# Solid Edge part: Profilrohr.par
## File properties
Username: bmolnar
Dokumentum tartalom típus: 0
Author: bmolnar
Last saved by: bmolnar
Revision: 92
Sűrűség: 0,000 kg/m^3
Pontosság: 0,990
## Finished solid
Body 1: solid body, 59 faces, 170 edges, 112 vertices.
  Faces by surface: plane 30, cylinder 29
  Edges by curve: line 112, circle 58
Bounding box of the edges (mm): 40.000 x 214.000 x 40.000, from (-20, -9.5, -20) to (20, 204.5, 20).
Cylindrical faces by radius (mm): R0.2 x12, R0.5 x12, R5 x4, R12.5 x1
Planar faces by outward normal: +x 7, +y 1, +z 7, -x 7, -y 1, -z 7
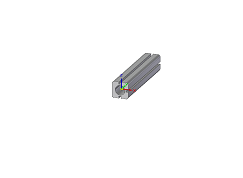
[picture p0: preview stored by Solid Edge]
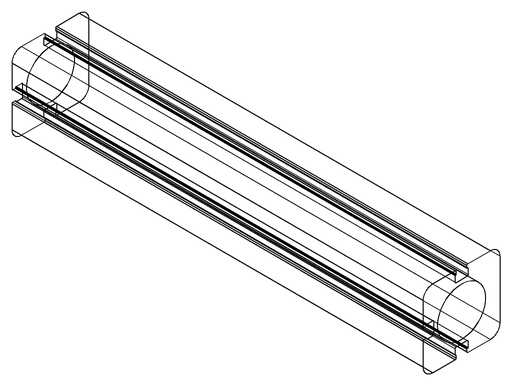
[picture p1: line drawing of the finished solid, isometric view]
